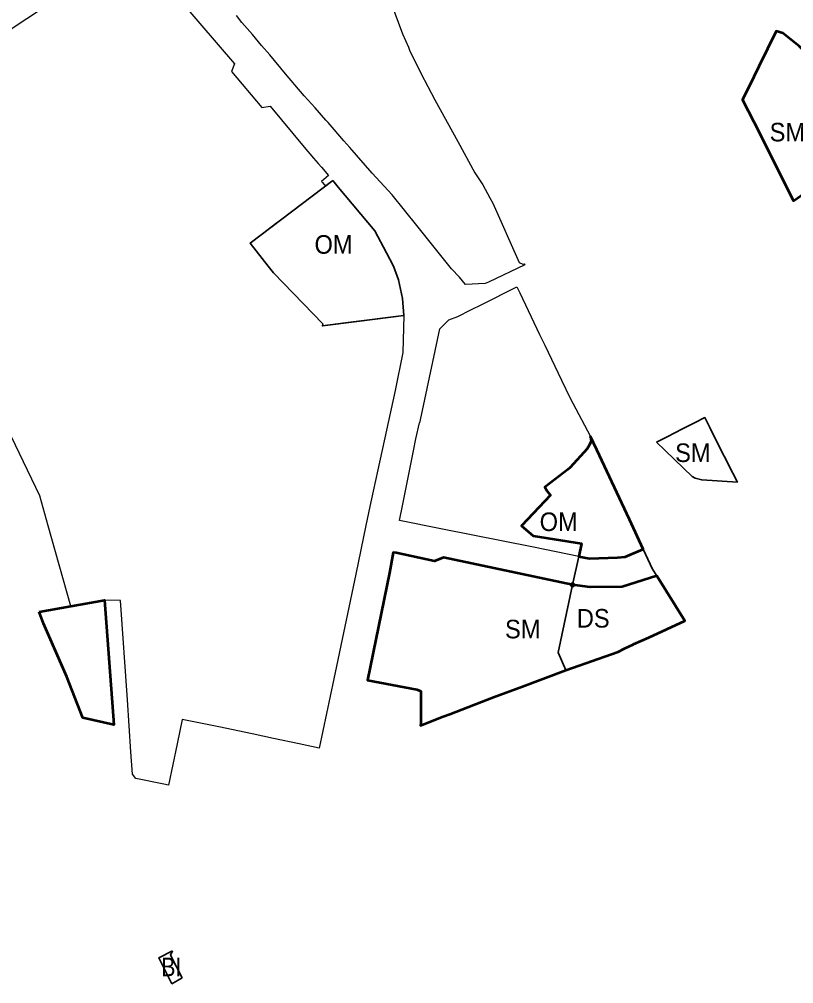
# Model space of a CAD drawing. Extents: x -650276 to -642489, y -1074311 to -1066658.
# Drawn here: x -647429 to -646929, y -1071700 to -1071077 of the extents above; entities that cross this region are included whole.
import ezdxf

# ---------------------------------------------------------------- set-up
doc = ezdxf.new("R2010")
doc.units = 0
doc.header["$LTSCALE"] = 4.8
doc.header["$PDMODE"] = 32
doc.header["$PDSIZE"] = 2.4
for name, color, linetype, lineweight in [('12', 7, 'Continuous', 35), ('15', 7, 'Continuous', 35), ('18', 7, 'Continuous', 35), ('2', 7, 'Continuous', 35), ('24', 7, 'Continuous', 35), ('60', 7, 'Continuous', 53), ('61', 7, 'Continuous', 25)]:
    doc.layers.add(name, color=color, linetype=linetype, lineweight=lineweight)
doc.layers.add('62', color=7, linetype='Continuous')

msp = doc.modelspace()

# ---------------------------------------------------------------- linework, layer by layer
at = {"layer": '12'}
for points in [[(-647226.895, -1071181.511), (-647280.14, -1071221.92), (-647268.52, -1071236.78), (-647265.15, -1071241.1), (-647233.34, -1071274.07), (-647233.64, -1071275.42), (-647218.75, -1071273.32), (-647181.12, -1071268.66), (-647181.99, -1071257.66), (-647184.58, -1071245.67), (-647187.68, -1071236.74), (-647192.29, -1071228.1), (-647199.82, -1071213.98), (-647223.46, -1071185.83)], [(-647056.48, -1071355.32), (-647060.6, -1071346.87), (-647060.22, -1071349.87), (-647061.4, -1071352.51), (-647062.78, -1071354.77), (-647073.68, -1071366.75), (-647075.25, -1071368.01), (-647083.48, -1071374.62), (-647090.04, -1071379.44), (-647088.57, -1071381.97), (-647086.45, -1071384.59), (-647105.2, -1071404.54), (-647097.5, -1071410.96), (-647066.35, -1071415.79), (-647068.162, -1071424.298), (-647061.23, -1071425.434), (-647043.137, -1071424.978), (-647038.119, -1071424.37), (-647026.472, -1071419.614), (-647035.47, -1071400.31)]]:
    msp.add_lwpolyline(points, close=True, dxfattribs=at)
at = {"layer": '15'}
for points in [[(-647072.11, -1071442.6), (-647060.812, -1071444.006), (-647040.089, -1071443.76), (-647017.7, -1071436.79), (-647020.52, -1071432.42), (-647026.472, -1071419.614)], [(-647026.472, -1071419.614), (-647038.119, -1071424.37), (-647043.137, -1071424.978), (-647061.23, -1071425.434), (-647068.162, -1071424.298)], [(-647068.162, -1071424.298), (-647068.162, -1071424.298), (-647072.11, -1071442.6)]]:
    msp.add_lwpolyline(points, dxfattribs=at)
msp.add_point((-647072.11, -1071442.6), dxfattribs=at)
at = {"layer": '18'}
for points in [[(-646951.831, -1071107.765), (-646955.138, -1071114.466), (-646962.471, -1071129.325), (-646955.2, -1071143.67), (-646929.64, -1071194.58), (-646899.85, -1071173.89), (-646881.68, -1071161.83), (-646879.91, -1071161.24), (-646881.97, -1071155.84), (-646887.07, -1071145.66), (-646890.59, -1071140.39), (-646896.62, -1071133.93), (-646904.64, -1071123.54), (-646906.72, -1071120.46), (-646920.54, -1071099.98), (-646925.88, -1071094.68), (-646936.51, -1071086.33), (-646940.67, -1071085.15), (-646940.67, -1071085.15)], [(-647017.93, -1071350.33), (-647013.15, -1071348.01), (-647004.02, -1071343.32), (-647003.37, -1071342.99), (-646993.38, -1071337.85), (-646986.69, -1071334.53), (-646983.33, -1071341.44), (-646977.95, -1071352.38), (-646974.28, -1071359.48), (-646968.63, -1071370.46), (-646965.74, -1071376.18), (-646988.77, -1071374.77), (-646992.95, -1071373.61), (-646994.85, -1071372.49)], [(-647072.11, -1071442.6), (-647155.36, -1071425), (-647161.2, -1071427.33), (-647185.99, -1071421.98), (-647187.85, -1071421.58), (-647190.4, -1071434.75), (-647204.42, -1071504.1), (-647172.74, -1071510.15), (-647170.01, -1071511.22), (-647170.18, -1071532.22), (-647170.23, -1071533.44), (-647155.58, -1071527.62), (-647151.28, -1071525.99), (-647123.17, -1071515.01), (-647104.47, -1071508.08), (-647076.46, -1071497.69), (-647081.488, -1071486.251)]]:
    msp.add_lwpolyline(points, close=True, dxfattribs=at)
at = {"layer": '2'}
for points in [[(-647330.34, -1071678.82), (-647339.211, -1071683.431), (-647330.73, -1071700.09)], [(-647330.73, -1071700.09), (-647324.21, -1071696.2), (-647331.65, -1071681.7), (-647330.34, -1071678.82)]]:
    msp.add_lwpolyline(points, dxfattribs=at)
at = {"layer": '24'}
msp.add_line((-647081.488, -1071486.251), (-647076.46, -1071497.69), dxfattribs=at)
for points in [[(-647017.7, -1071436.79), (-647040.089, -1071443.76), (-647060.812, -1071444.006), (-647072.11, -1071442.6), (-647081.488, -1071486.251)], [(-647076.46, -1071497.69), (-647042.78, -1071485.76), (-647022.81, -1071476.61), (-646999.77, -1071465.81), (-647017.7, -1071436.79)]]:
    msp.add_lwpolyline(points, dxfattribs=at)
at = {"layer": '60'}
for points in [[(-646951.831, -1071107.765), (-646955.138, -1071114.466), (-646962.471, -1071129.325), (-646955.2, -1071143.67), (-646929.64, -1071194.58), (-646899.85, -1071173.89), (-646881.68, -1071161.83), (-646879.91, -1071161.24), (-646881.97, -1071155.84), (-646887.07, -1071145.66), (-646890.59, -1071140.39), (-646896.62, -1071133.93), (-646904.64, -1071123.54), (-646906.72, -1071120.46), (-646920.54, -1071099.98), (-646925.88, -1071094.68), (-646936.51, -1071086.33), (-646940.67, -1071085.15)], [(-647056.48, -1071355.32), (-647060.6, -1071346.87), (-647060.22, -1071349.87), (-647061.4, -1071352.51), (-647062.78, -1071354.77), (-647073.68, -1071366.75), (-647075.25, -1071368.01), (-647083.48, -1071374.62), (-647090.04, -1071379.44), (-647088.57, -1071381.97), (-647086.45, -1071384.59), (-647105.2, -1071404.54), (-647097.5, -1071410.96), (-647066.35, -1071415.79), (-647068.162, -1071424.298), (-647061.23, -1071425.434), (-647043.137, -1071424.978), (-647038.119, -1071424.37), (-647026.472, -1071419.614), (-647035.47, -1071400.31)], [(-647072.11, -1071442.6), (-647155.36, -1071425), (-647161.2, -1071427.33), (-647185.99, -1071421.98), (-647187.85, -1071421.58), (-647190.4, -1071434.75), (-647204.42, -1071504.1), (-647172.74, -1071510.15), (-647170.01, -1071511.22), (-647170.18, -1071532.22), (-647170.23, -1071533.44), (-647155.58, -1071527.62), (-647151.28, -1071525.99), (-647123.17, -1071515.01), (-647104.47, -1071508.08), (-647076.46, -1071497.69), (-647042.78, -1071485.76), (-647038.62, -1071483.74), (-647033.09, -1071481.06), (-647032.73, -1071480.88), (-647022.81, -1071476.61), (-646999.77, -1071465.81), (-647017.7, -1071436.79), (-647040.089, -1071443.76), (-647060.812, -1071444.006)], [(-647416.42, -1071460.03), (-647396.02, -1071456.32), (-647374.2, -1071452.36), (-647368.26, -1071532.99), (-647388.29, -1071528.41), (-647398.64, -1071501.96), (-647413.54, -1071467.53)]]:
    msp.add_lwpolyline(points, close=True, dxfattribs=at)
at = {"layer": '61'}
for points in [[(-647442.36, -1071088.82), (-647406.52, -1071065.05)], [(-647324.46, -1071066.41), (-647290.44, -1071106.08), (-647292.31, -1071111.16), (-647272.8, -1071134.42), (-647267.4, -1071133.54), (-647245.43, -1071159.88), (-647239.35, -1071166.98), (-647236.41, -1071170.41), (-647234.12, -1071172.97), (-647229.71, -1071178.23), (-647234.22, -1071182.02), (-647233.57, -1071182.82), (-647231.69, -1071185.15), (-647262.35, -1071208.42), (-647263.8, -1071209.52), (-647278.04, -1071220.33), (-647280.14, -1071221.92), (-647268.52, -1071236.78), (-647265.15, -1071241.1), (-647233.34, -1071274.07), (-647233.64, -1071275.42), (-647209.66, -1071272.22), (-647181.12, -1071268.66), (-647181.79, -1071292.49), (-647186.6, -1071316.98), (-647197.87, -1071368.22), (-647200.76, -1071382.02), (-647202.98, -1071391.98), (-647205.52, -1071404.32), (-647212.07, -1071435.71), (-647226.296, -1071503.249), (-647235.71, -1071547.94), (-647248.51, -1071545.3), (-647265.23, -1071541.68), (-647278.94, -1071538.77), (-647300.51, -1071534.33), (-647324.04, -1071529.54), (-647327.31, -1071545.25), (-647332.86, -1071571.94), (-647335.88, -1071571.31), (-647353.95, -1071567.53), (-647356.2, -1071564.75), (-647357.15, -1071550.44), (-647359.38, -1071516.88), (-647363.86, -1071452.66), (-647374.2, -1071452.36), (-647396.02, -1071456.32), (-647410.56, -1071404.35), (-647415.97, -1071385.01), (-647445, -1071324.99)], [(-647189.68, -1071065.99), (-647181.99, -1071086.74), (-647178.11, -1071095.31), (-647177.46, -1071097.42), (-647170.18, -1071112.08), (-647161.13, -1071129.3), (-647146.28, -1071156.35), (-647135.21, -1071176.44), (-647130.1, -1071184.33), (-647125.44, -1071192.58), (-647123.7, -1071196.19), (-647106.7, -1071234.45), (-647104.17, -1071235.6), (-647103.31, -1071235.22), (-647102.97, -1071235.92), (-647126.477, -1071247.083), (-647128.45, -1071248.02), (-647141.14, -1071248.62), (-647145.16, -1071243.92), (-647150.32, -1071238.51), (-647169.11, -1071214.8), (-647172.63, -1071210.63), (-647188.68, -1071190.78), (-647201.42, -1071176.7), (-647215.86, -1071160.1), (-647219.82, -1071155.78), (-647229.97, -1071144.1), (-647231.32, -1071142.57), (-647238.29, -1071134.66), (-647245.31, -1071126.75), (-647257.41, -1071112.55), (-647267.64, -1071100.44), (-647272.93, -1071094.24), (-647278.77, -1071087.15), (-647285.53, -1071079.39), (-647289.1, -1071074.88)]]:
    msp.add_lwpolyline(points, dxfattribs=at)
msp.add_lwpolyline([(-647093.11, -1071411.77), (-647066.35, -1071415.79), (-647068.162, -1071424.298), (-647097.427, -1071418.318), (-647157.231, -1071406.28), (-647183.816, -1071400.974), (-647181.75, -1071390.51), (-647174.73, -1071356.1), (-647173.24, -1071348.27), (-647170.96, -1071337.84), (-647170.63, -1071337.91), (-647168.91, -1071329.88), (-647157.83, -1071277.35), (-647152.09, -1071271.47), (-647146.3, -1071269.33), (-647137.84, -1071265.06), (-647130.76, -1071261.49), (-647108.16, -1071250.08), (-647106.233, -1071254.01), (-647093.39, -1071280.83), (-647090, -1071287.89), (-647079.25, -1071310.33), (-647073.98, -1071321.53), (-647060.6, -1071346.87), (-647060.22, -1071349.87), (-647061.4, -1071352.51), (-647062.78, -1071354.77), (-647073.68, -1071366.75), (-647075.25, -1071368.01), (-647083.48, -1071374.62), (-647083.48, -1071374.62), (-647090.04, -1071379.44), (-647086.45, -1071384.59), (-647105.2, -1071404.54), (-647097.5, -1071410.96)], close=True, dxfattribs=at)

# ---------------------------------------------------------------- texts
at = {"layer": '62'}
for s, width, p in [('SM', 0.95, (-646944.938, -1071156.245)), ('OM', 0.95, (-647238.703, -1071228.756)), ('SM', 0.95, (-647005.938, -1071363.245)), ('OM', 0.95, (-647093.38, -1071407.817)), ('DS', 0.95, (-647069.386, -1071470.148)), ('SM', 0.95, (-647115.735, -1071477.109)), ('BI', 0.85, (-647337.578, -1071695.247))]:
    msp.add_text(s, height=12, dxfattribs=dict(at, width=width)).set_placement(p)

doc.saveas('drawing.dxf')
